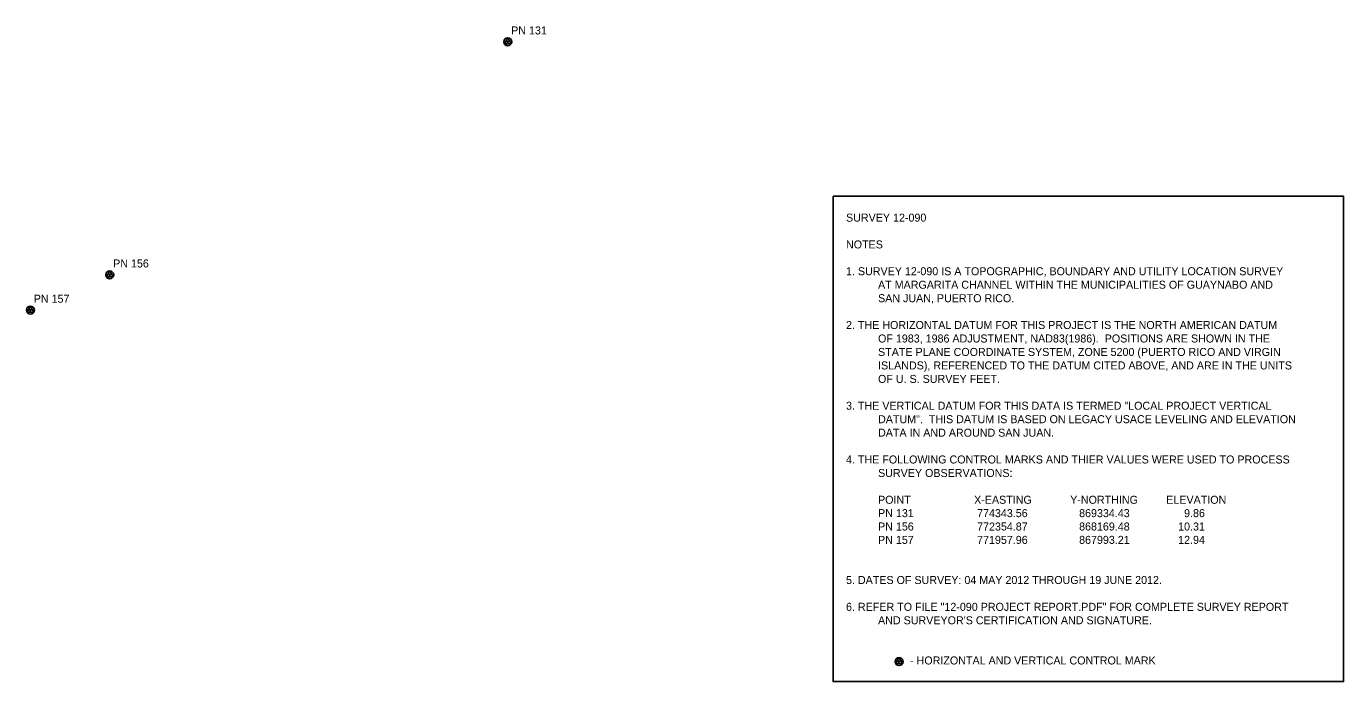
# Model space of a CAD drawing. Extents: x 771938 to 778520, y 866136 to 869412.
import ezdxf

# ---------------------------------------------------------------- set-up
doc = ezdxf.new("R2010")
doc.units = 0
for name, color, linetype in [('V-ANNO-NOTE', 7, 'Continuous'), ('V-ANNO-TEXT', 7, 'Continuous'), ('V-CTRL-HVPT', 7, 'Continuous')]:
    doc.layers.add(name, color=color, linetype=linetype)

# ---------------------------------------------------------------- blocks, each defined once
blk = doc.blocks.new('HOVCPT')
at = {"layer": 'V-CTRL-HVPT'}
for p, q in [((-0.043, -0.025), (0, 0.05)), ((0, 0.05), (0.043, -0.025)), ((0.043, -0.025), (-0.043, -0.025))]:
    blk.add_line(p, q, dxfattribs=at)
for radius in [0.05, 0.00734]:
    blk.add_circle((0, 0), radius, dxfattribs=at)

msp = doc.modelspace()

# ---------------------------------------------------------------- linework, layer by layer
at = {"layer": 'V-ANNO-NOTE'}
msp.add_lwpolyline([(775969.4, 868562.6), (778520.2, 868562.6), (778520.2, 866135.7), (775969.4, 866135.7)], close=True, dxfattribs=at)

# ---------------------------------------------------------------- block references
at = {"layer": 'V-CTRL-HVPT', "xscale": 400, "yscale": 400}
for p in [(774343.6, 869334.4), (772354.9, 868169.5), (771958, 867993.2), (776298.8, 866236.1)]:
    msp.add_blockref('HOVCPT', p, dxfattribs=at)

# ---------------------------------------------------------------- texts
at = {"layer": 'V-ANNO-NOTE'}
for s, p in [('SURVEY 12-090', (776033.7, 868435.5)), ('NOTES', (776033.7, 868301.5)), ('1. SURVEY 12-090 IS A TOPOGRAPHIC, BOUNDARY AND UTILITY LOCATION SURVEY', (776033.7, 868167.5)), ('AT MARGARITA CHANNEL WITHIN THE MUNICIPALITIES OF GUAYNABO AND', (776193.7, 868100.1)), ('SAN JUAN, PUERTO RICO.', (776193.7, 868032.7)), ('2. THE HORIZONTAL DATUM FOR THIS PROJECT IS THE NORTH AMERICAN DATUM', (776033.7, 867898.7)), ('OF 1983, 1986 ADJUSTMENT, NAD83(1986).  POSITIONS ARE SHOWN IN THE', (776193.7, 867831.3)), ('STATE PLANE COORDINATE SYSTEM, ZONE 5200 (PUERTO RICO AND VIRGIN', (776193.7, 867764)), ('ISLANDS), REFERENCED TO THE DATUM CITED ABOVE, AND ARE IN THE UNITS', (776193.7, 867696.6)), ('OF U. S. SURVEY FEET.', (776193.7, 867629.2)), ('3. THE VERTICAL DATUM FOR THIS DATA IS TERMED "LOCAL PROJECT VERTICAL', (776033.7, 867495.2)), ('DATUM".  THIS DATUM IS BASED ON LEGACY USACE LEVELING AND ELEVATION', (776193.7, 867427.8)), ('DATA IN AND AROUND SAN JUAN.', (776193.7, 867360.4)), ('4. THE FOLLOWING CONTROL MARKS AND THIER VALUES WERE USED TO PROCESS', (776033.7, 867226.4)), ('SURVEY OBSERVATIONS:', (776193.7, 867159)), ('POINT', (776193.7, 867025)), ('X-EASTING', (776673.7, 867025)), ('Y-NORTHING', (777153.7, 867025)), ('ELEVATION', (777633.7, 867025)), ('PN 131', (776193.7, 866958.2)), (' 774343.56', (776673.7, 866958.2)), ('   869334.43', (777153.7, 866958.2)), ('      9.86', (777633.7, 866958.2)), ('PN 156', (776193.7, 866891.4)), (' 772354.87', (776673.7, 866891.4)), ('   868169.48', (777153.7, 866891.4)), ('    10.31', (777633.7, 866891.4)), ('PN 157', (776193.7, 866824.6)), (' 771957.96', (776673.7, 866824.6)), ('   867993.21', (777153.7, 866824.6)), ('    12.94', (777633.7, 866824.6)), ('5. DATES OF SURVEY: 04 MAY 2012 THROUGH 19 JUNE 2012.', (776033.7, 866623.9)), ('6. REFER TO FILE "12-090 PROJECT REPORT.PDF" FOR COMPLETE SURVEY REPORT', (776033.7, 866489.8)), ("AND SURVEYOR'S CERTIFICATION AND SIGNATURE.", (776193.7, 866422.5)), ('- HORIZONTAL AND VERTICAL CONTROL MARK', (776353.7, 866221.7))]:
    msp.add_text(s, height=40, dxfattribs=at).set_placement(p)
at = {"layer": 'V-ANNO-TEXT'}
for s, p in [('PN 131', (774360.4, 869371.2)), ('PN 156', (772371.7, 868206.3)), ('PN 157', (771974.8, 868030))]:
    msp.add_text(s, height=40, dxfattribs=at).set_placement(p)

doc.saveas('drawing.dxf')
